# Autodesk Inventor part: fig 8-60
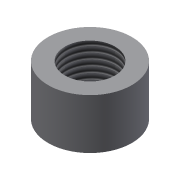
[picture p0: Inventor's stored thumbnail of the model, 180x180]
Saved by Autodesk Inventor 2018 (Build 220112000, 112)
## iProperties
Shininess: 77.0
Length Units: 11269
Angle Units: 11279
Time Units: 11290
Mass Units: 11283
Length Display Precision: 3
Angle Display Precision: 2
Compacted: True
Created: 2002-01
Part Number: fig 8-60
Document SubType Name: Modeling
Designer: ***
Density: 1 g/cm^3
Material: Generic
Appearance: Default
Density: 0.0
Volumn: 0.0
Area: 0.0
PropertySet Name: Model Information
Control State: 0
Master: False
Checked Out: False
Author: ***
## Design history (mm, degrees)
sketch "Sketch1"
  geometry: C1 r 25 at (0, 0); C2 r 15 at (0, 0)
  constraints: 2 centre point, 1 coincident
  dimensions: "d0" = 50 diameter of C1; "d1" = 30 diameter of C2
extrude "Extrusion1" new body sketch "Sketch1" distance "d2" = 30; taper "d3" = 0 deg
thread "Thread5" dims "d12" = 10, "d13" = 0
body "Solid1"
